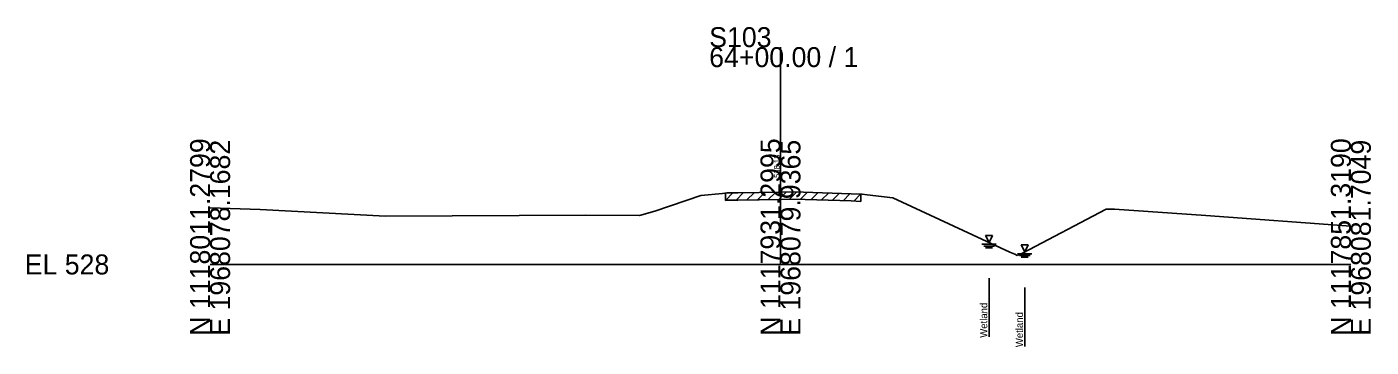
# Model space of a CAD drawing. Extents: x -26 to 163, y -10 to 45020.
# Drawn here: x -25.7 to 162.8, y 22988.4 to 23033.3 of the extents above; entities that cross this region are included whole.
import ezdxf

# ---------------------------------------------------------------- set-up
doc = ezdxf.new("R2010")
doc.units = 0
for name, color, linetype in [('RD_GPK_XS_Cell', 7, 'Continuous'), ('RD_XS_ExGround', 7, 'Continuous'), ('RD_XS_ExPaveRet', 7, 'Continuous'), ('RD_XS_EXWetland', 7, 'Continuous'), ('RD_XS_TX_Elev_EX', 7, 'Continuous')]:
    doc.layers.add(name, color=color, linetype=linetype)

msp = doc.modelspace()

# ---------------------------------------------------------------- linework, layer by layer
at = {"layer": 'RD_GPK_XS_Cell'}
for p, q in [((80, 23000), (80, 23030.48)), ((0, 23000), (80, 23000)), ((80, 23000), (160, 23000))]:
    msp.add_line(p, q, dxfattribs=at)
at = {"layer": 'RD_XS_ExGround'}
for p, q in [((62.37, 23007.47), (68.81, 23009.65)), ((68.81, 23009.65), (71.88, 23009.95)), ((71.88, 23009.95), (72.48, 23010.02)), ((72.48, 23010.02), (74.04, 23010.02)), ((74.04, 23010.02), (80, 23010.13)), ((80, 23010.13), (81.89, 23010.16)), ((81.89, 23010.16), (89.91, 23009.91)), ((89.91, 23009.91), (91.44, 23009.84)), ((91.44, 23009.84), (92.15, 23009.77)), ((92.15, 23009.77), (95.74, 23009.32)), ((95.74, 23009.32), (112.19, 23001.73)), ((0, 23007.94), (7.01, 23007.72)), ((7.01, 23007.72), (24.6, 23006.78)), ((24.6, 23006.78), (52.68, 23006.92)), ((52.68, 23006.92), (60.25, 23006.88)), ((60.25, 23006.88), (62.37, 23007.47)), ((113.95, 23001.59), (125.7, 23007.77)), ((125.7, 23007.77), (126.86, 23007.74)), ((126.86, 23007.74), (139.64, 23006.87)), ((139.64, 23006.87), (160, 23005.35)), ((112.19, 23001.73), (112.87, 23001.46)), ((112.87, 23001.46), (113.22, 23001.24)), ((113.22, 23001.24), (113.95, 23001.59))]:
    msp.add_line(p, q, dxfattribs=at)
at = {"layer": 'RD_XS_ExPaveRet'}
for p, q in [((72.27, 23008.99), (73.3, 23010.02)), ((72.27, 23008.99), (72.27, 23009.99)), ((72.27, 23008.99), (72.48, 23009.02)), ((72.48, 23009.02), (74.04, 23009.02)), ((73.77, 23009.02), (74.79, 23010.04)), ((74.04, 23009.02), (80, 23009.13)), ((75.27, 23009.04), (76.29, 23010.06)), ((76.77, 23009.07), (77.79, 23010.09)), ((78.27, 23009.1), (79.29, 23010.11)), ((79.77, 23009.12), (80.79, 23010.14)), ((80, 23009.13), (81.89, 23009.16)), ((81.27, 23009.15), (82.27, 23010.15)), ((81.89, 23009.16), (89.91, 23008.91)), ((82.77, 23009.13), (83.74, 23010.1)), ((84.27, 23009.08), (85.24, 23010.05)), ((85.77, 23009.04), (86.74, 23010.01)), ((87.27, 23008.99), (88.24, 23009.96)), ((88.77, 23008.94), (89.74, 23009.91)), ((89.91, 23008.91), (91.25, 23008.85)), ((90.27, 23008.89), (91.23, 23009.85)), ((91.25, 23009.85), (91.25, 23008.85))]:
    msp.add_line(p, q, dxfattribs=at)
at = {"layer": 'RD_XS_EXWetland'}
for p, q in [((108.75, 23004.08), (109.25, 23003.08)), ((109.75, 23004.08), (108.75, 23004.08)), ((109.25, 23003.08), (109.75, 23004.08)), ((108.25, 23002.83), (110.25, 23002.83)), ((108.5, 23002.58), (110, 23002.58)), ((108.75, 23002.33), (109.75, 23002.33)), ((113.26, 23001.5), (115.26, 23001.5)), ((113.51, 23001.25), (115.01, 23001.25)), ((113.76, 23002.75), (114.26, 23001.75)), ((114.76, 23002.75), (113.76, 23002.75)), ((113.76, 23001), (114.76, 23001)), ((114.26, 23001.75), (114.76, 23002.75)), ((109.25, 22998.08), (109.25, 22989.83)), ((114.26, 22996.75), (114.26, 22988.5))]:
    msp.add_line(p, q, dxfattribs=at)

# ---------------------------------------------------------------- texts
at = {"layer": 'RD_GPK_XS_Cell'}
for s, p in [('S103', (70, 23030.48)), ('64+00.00 / 1', (70, 23027.68)), ('EL 528', (-26, 22998.6))]:
    msp.add_text(s, height=2.8, dxfattribs=at).set_placement(p)
for s, p in [('N 1118011.2799', (0, 22990)), ('E 1968078.1682', (2.8, 22990)), ('N 1117931.2995', (80, 22990)), ('E 1968079.9365', (82.8, 22990)), ('N 1117851.3190', (160, 22990)), ('E 1968081.7049', (162.8, 22990))]:
    msp.add_text(s, height=2.8, rotation=90, dxfattribs=at).set_placement(p)
at = {"layer": 'RD_XS_EXWetland'}
for p in [(109, 22989.72), (114.01, 22988.4)]:
    msp.add_text('Wetland ', height=1, rotation=90, dxfattribs=at).set_placement(p)
at = {"layer": 'RD_XS_TX_Elev_EX'}
msp.add_text('538.13', height=0.8, rotation=90, dxfattribs=at).set_placement((79.9, 23012.13))

doc.saveas('drawing.dxf')
